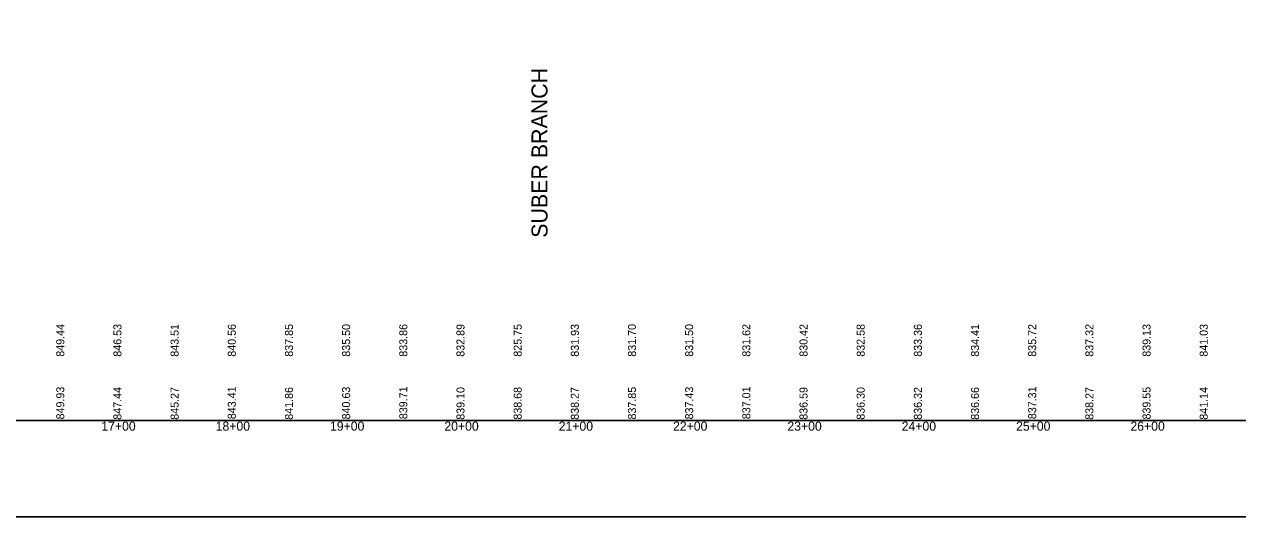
# Model space of a CAD drawing. Extents: x 1624623 to 1634359, y 1111996 to 1119862.
# Drawn here: x 1632341 to 1633403, y 1111996 to 1112427 of the extents above; entities that cross this region are included whole.
import ezdxf

# ---------------------------------------------------------------- set-up
doc = ezdxf.new("R2010")
doc.units = 0
for name, color, linetype in [('RD_EV_JW', 7, 'Continuous'), ('RD_HC_Data_Tic', 7, 'Continuous'), ('RD_PD_CstnLmt', 7, 'Continuous'), ('RD_PD_Final_TrvlWay', 7, 'Continuous'), ('RD_Sketch9', 7, 'Continuous')]:
    doc.layers.add(name, color=color, linetype=linetype)

msp = doc.modelspace()

# ---------------------------------------------------------------- linework, layer by layer
at = {"layer": 'RD_HC_Data_Tic'}
msp.add_line((1631726.3, 1112080.1), (1634359.4, 1112080.1), dxfattribs=at)
at = {"layer": 'RD_Sketch9'}
msp.add_lwpolyline([(1631923.2, 1113095.7), (1633723.2, 1113095.7), (1633723.2, 1111995.7), (1631923.2, 1111995.7)], close=True, dxfattribs=at)

# ---------------------------------------------------------------- texts
at = {"layer": 'RD_EV_JW'}
msp.add_text('SUBER BRANCH', height=14, rotation=90, dxfattribs=at).set_placement((1632798.9, 1112240))
at = {"layer": 'RD_PD_CstnLmt'}
for s, p in [('17+00', (1632408.7, 1112071.1)), ('18+00', (1632508.7, 1112071.1)), ('19+00', (1632608.7, 1112071.1)), ('20+00', (1632708.7, 1112071.1)), ('21+00', (1632808.7, 1112071.1)), ('22+00', (1632908.7, 1112071.1)), ('23+00', (1633008.7, 1112071.1)), ('24+00', (1633108.7, 1112071.1)), ('25+00', (1633208.7, 1112071.1)), ('26+00', (1633308.7, 1112071.1))]:
    msp.add_text(s, height=8, dxfattribs=at).set_placement(p)
at = {"layer": 'RD_PD_Final_TrvlWay'}
for s, p in [('849.44', (1632376.3, 1112135.9)), ('846.53', (1632426.3, 1112135.9)), ('843.51', (1632476.3, 1112135.9)), ('840.56', (1632526.3, 1112135.9)), ('837.85', (1632576.3, 1112135.9)), ('835.50', (1632626.3, 1112135.9)), ('833.86', (1632676.3, 1112135.9)), ('832.89', (1632726.3, 1112135.9)), ('825.75', (1632776.3, 1112135.9)), ('831.93', (1632826.3, 1112135.9)), ('831.70', (1632876.3, 1112135.9)), ('831.50', (1632926.3, 1112135.9)), ('831.62', (1632976.3, 1112135.9)), ('830.42', (1633026.3, 1112135.9)), ('832.58', (1633076.3, 1112135.9)), ('833.36', (1633126.3, 1112135.9)), ('834.41', (1633176.3, 1112135.9)), ('835.72', (1633226.3, 1112135.9)), ('837.32', (1633276.3, 1112135.9)), ('839.13', (1633326.3, 1112135.9)), ('841.03', (1633376.3, 1112135.9)), ('849.93', (1632376.3, 1112081)), ('847.44', (1632426.3, 1112080.7)), ('845.27', (1632476.3, 1112080.7)), ('843.41', (1632526.3, 1112081.2)), ('841.86', (1632576.3, 1112080.7)), ('840.63', (1632626.3, 1112081)), ('839.71', (1632676.3, 1112081.2)), ('839.10', (1632726.3, 1112080.7)), ('838.68', (1632776.3, 1112080.8)), ('838.27', (1632826.3, 1112080.7)), ('837.85', (1632876.3, 1112080.9)), ('837.43', (1632926.3, 1112081)), ('837.01', (1632976.3, 1112081.2)), ('836.59', (1633026.3, 1112080.7)), ('836.30', (1633076.3, 1112080.7)), ('836.32', (1633126.3, 1112080.7)), ('836.66', (1633176.3, 1112080.7)), ('837.31', (1633226.3, 1112081.2)), ('838.27', (1633276.3, 1112080.7)), ('839.55', (1633326.3, 1112080.9)), ('841.14', (1633376.3, 1112080.7))]:
    msp.add_text(s, height=7, rotation=90, dxfattribs=at).set_placement(p)

doc.saveas('drawing.dxf')
